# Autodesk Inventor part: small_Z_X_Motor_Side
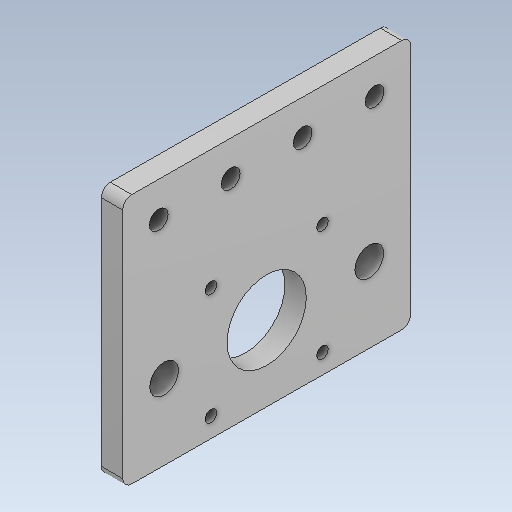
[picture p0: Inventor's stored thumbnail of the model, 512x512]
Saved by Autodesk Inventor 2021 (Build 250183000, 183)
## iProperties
Created: 2026-10
Part Number: small_Z_X_Motor_Side
Material: Steel
Document SubType Name: Modeling
Designer: hp
Density: 7.85 g/cm^3
Appearance: Default
Author: hp
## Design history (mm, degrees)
feature "Body1"
body "Solid1"
